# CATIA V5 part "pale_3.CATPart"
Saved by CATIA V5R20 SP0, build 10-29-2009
Part number: pale_3
Bounding box of the stored display mesh (mm): x 635.778 to 2685.778, y 741.325 to 1722.173, z -577.328 to -207.359
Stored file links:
  D:\thinkmotion-MPB\Dropbox\MMS_GR3\CFAO_2010_bfoltzer\CFAO_bfoltzer\pale_3.CATPart
  D:\ecole\thinkmotion\Eolienne.CATProduct
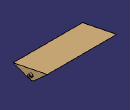
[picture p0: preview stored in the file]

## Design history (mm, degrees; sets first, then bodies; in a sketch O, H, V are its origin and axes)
External parameters (linked from other documents)
  External.rayon_barre = 20 mm
  External.largeur_pale = 300 mm
Set1
  Plane1: linked copy from another document
  Point1 to Point4: linked copy from another document
  Plane2: linked copy from another document
  Point5: linked copy from another document
  Plane3: linked copy from another document
  Plane4: linked copy from another document
  Point6: linked copy from another document
Body1 (main body)
  Sketch1 on Plane1, origin (635.7782, 0, 0), H (0, 1, 0), V (0, 0, 1)
    point P1 (741.3252, -402.1334)
    line L1 (1722.1733, -207.3593) -> (741.3252, -402.1334)
    point P2 (1722.1733, -207.3593)
    point P3 (741.3252, -402.1334)
    point P4 (1722.1733, -207.3593)
    reference projected point E1 (741.3252, -402.1334) from Point2
    reference projected point E2 (1722.1733, -207.3593) from Point3
    reference projected point E3 (1722.1733, -207.3593) from Point3
    reference projected point E4 (741.3252, -402.1334) from Point2
    line L2 (741.3252, -402.1334) -> (1290.1815, -599.0008)
    point P5 (741.3252, -402.1334)
    point P6 (1290.1815, -599.0008)
    reference projected point E5 (1290.1815, -599.0008) from Point1
    reference projected point E6 (741.3252, -402.1334) from Point2
    line L3 (1722.1733, -207.3593) -> (1290.1815, -599.0008)
    point P7 (1722.1733, -207.3593)
    point P8 (1290.1815, -599.0008)
    reference projected point E7 (1722.1733, -207.3593) from Point3
    reference projected point E8 (1290.1815, -599.0008) from Point6
    coincidence: P1 E1, P4 E2, P2 E3, P3 E4, P1 P3, P2 P4, P6 E5, P5 E6, P7 E7, P8 E8
  Pad1: profile Sketch1, direction (1, 0, 0), up to Plane2
  Sketch2 on Plane1, origin (635.7782, 0, 0), H (0, 1, 0), V (0, 0, 1)
    circle A1 centre (1260.9654, -451.8736) radius 50
    point P1 (1260.9654, -451.8736)
    reference projected point E1 (1260.9654, -451.8736) from Point4
    reference projected point E2 (1270.7041, -500.916) from Point5
    coincidence: P1 E1, A1 E2
  Pocket1: profile Sketch2, direction (-1, 0, 0), up to Plane3
  Pad2: profile Sketch2, direction (1, 0, 0), up to Plane2, opposite side up to Plane4
  Sketch3 on end face of Pocket1, origin (685.7782, 956.1024, -413.6247), H (0, 1, 0), V (0, 0, -1)
    point P1 (304.863, 38.2489)
    reference projected point E1 (304.863, 38.2489) from Point4
    coincidence: E1 P1
  Hole1: placed by Sketch3, at (685.7782, 1260.9654, -451.8736) direction (1, 0, 0), diameter 40 {= External.rayon_barre *2}, up to Plane4
  Fillet1: radius 150 {= External.largeur_pale /2}, on edge [face of Pad1 from Sketch1.L3 | face of Pad1 from Sketch1.L2]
